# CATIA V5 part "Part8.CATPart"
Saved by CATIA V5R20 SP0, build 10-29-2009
Part number: 9TS1206M5
Revision: ANY
Definition: UNKNOWN
Nomenclature: 9TS1206M5
Source: Unknown
Bounding box of the stored display mesh (mm): x -6 to 6, y -5.85 to 5.85, z 0 to 6
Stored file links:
  C:\Users\Utente\Desktop\IO LAVORO\3D X SITO CF\CUMSA\3D files GR\GR 182622-15\Part8.CATPart
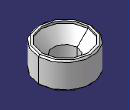
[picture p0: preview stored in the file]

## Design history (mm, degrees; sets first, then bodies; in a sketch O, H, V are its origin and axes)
Body1 "Chaflán2" (main body)
  Solid1: solid without history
